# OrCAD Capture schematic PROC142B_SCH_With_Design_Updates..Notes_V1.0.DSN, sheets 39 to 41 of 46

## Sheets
39 39. OLDI DISPLAY INTERFACE: size C; title: SOC OLDI INTERFACE, LCD CONNECTOR & SOC UART1 FET SWITCH & BUFFER
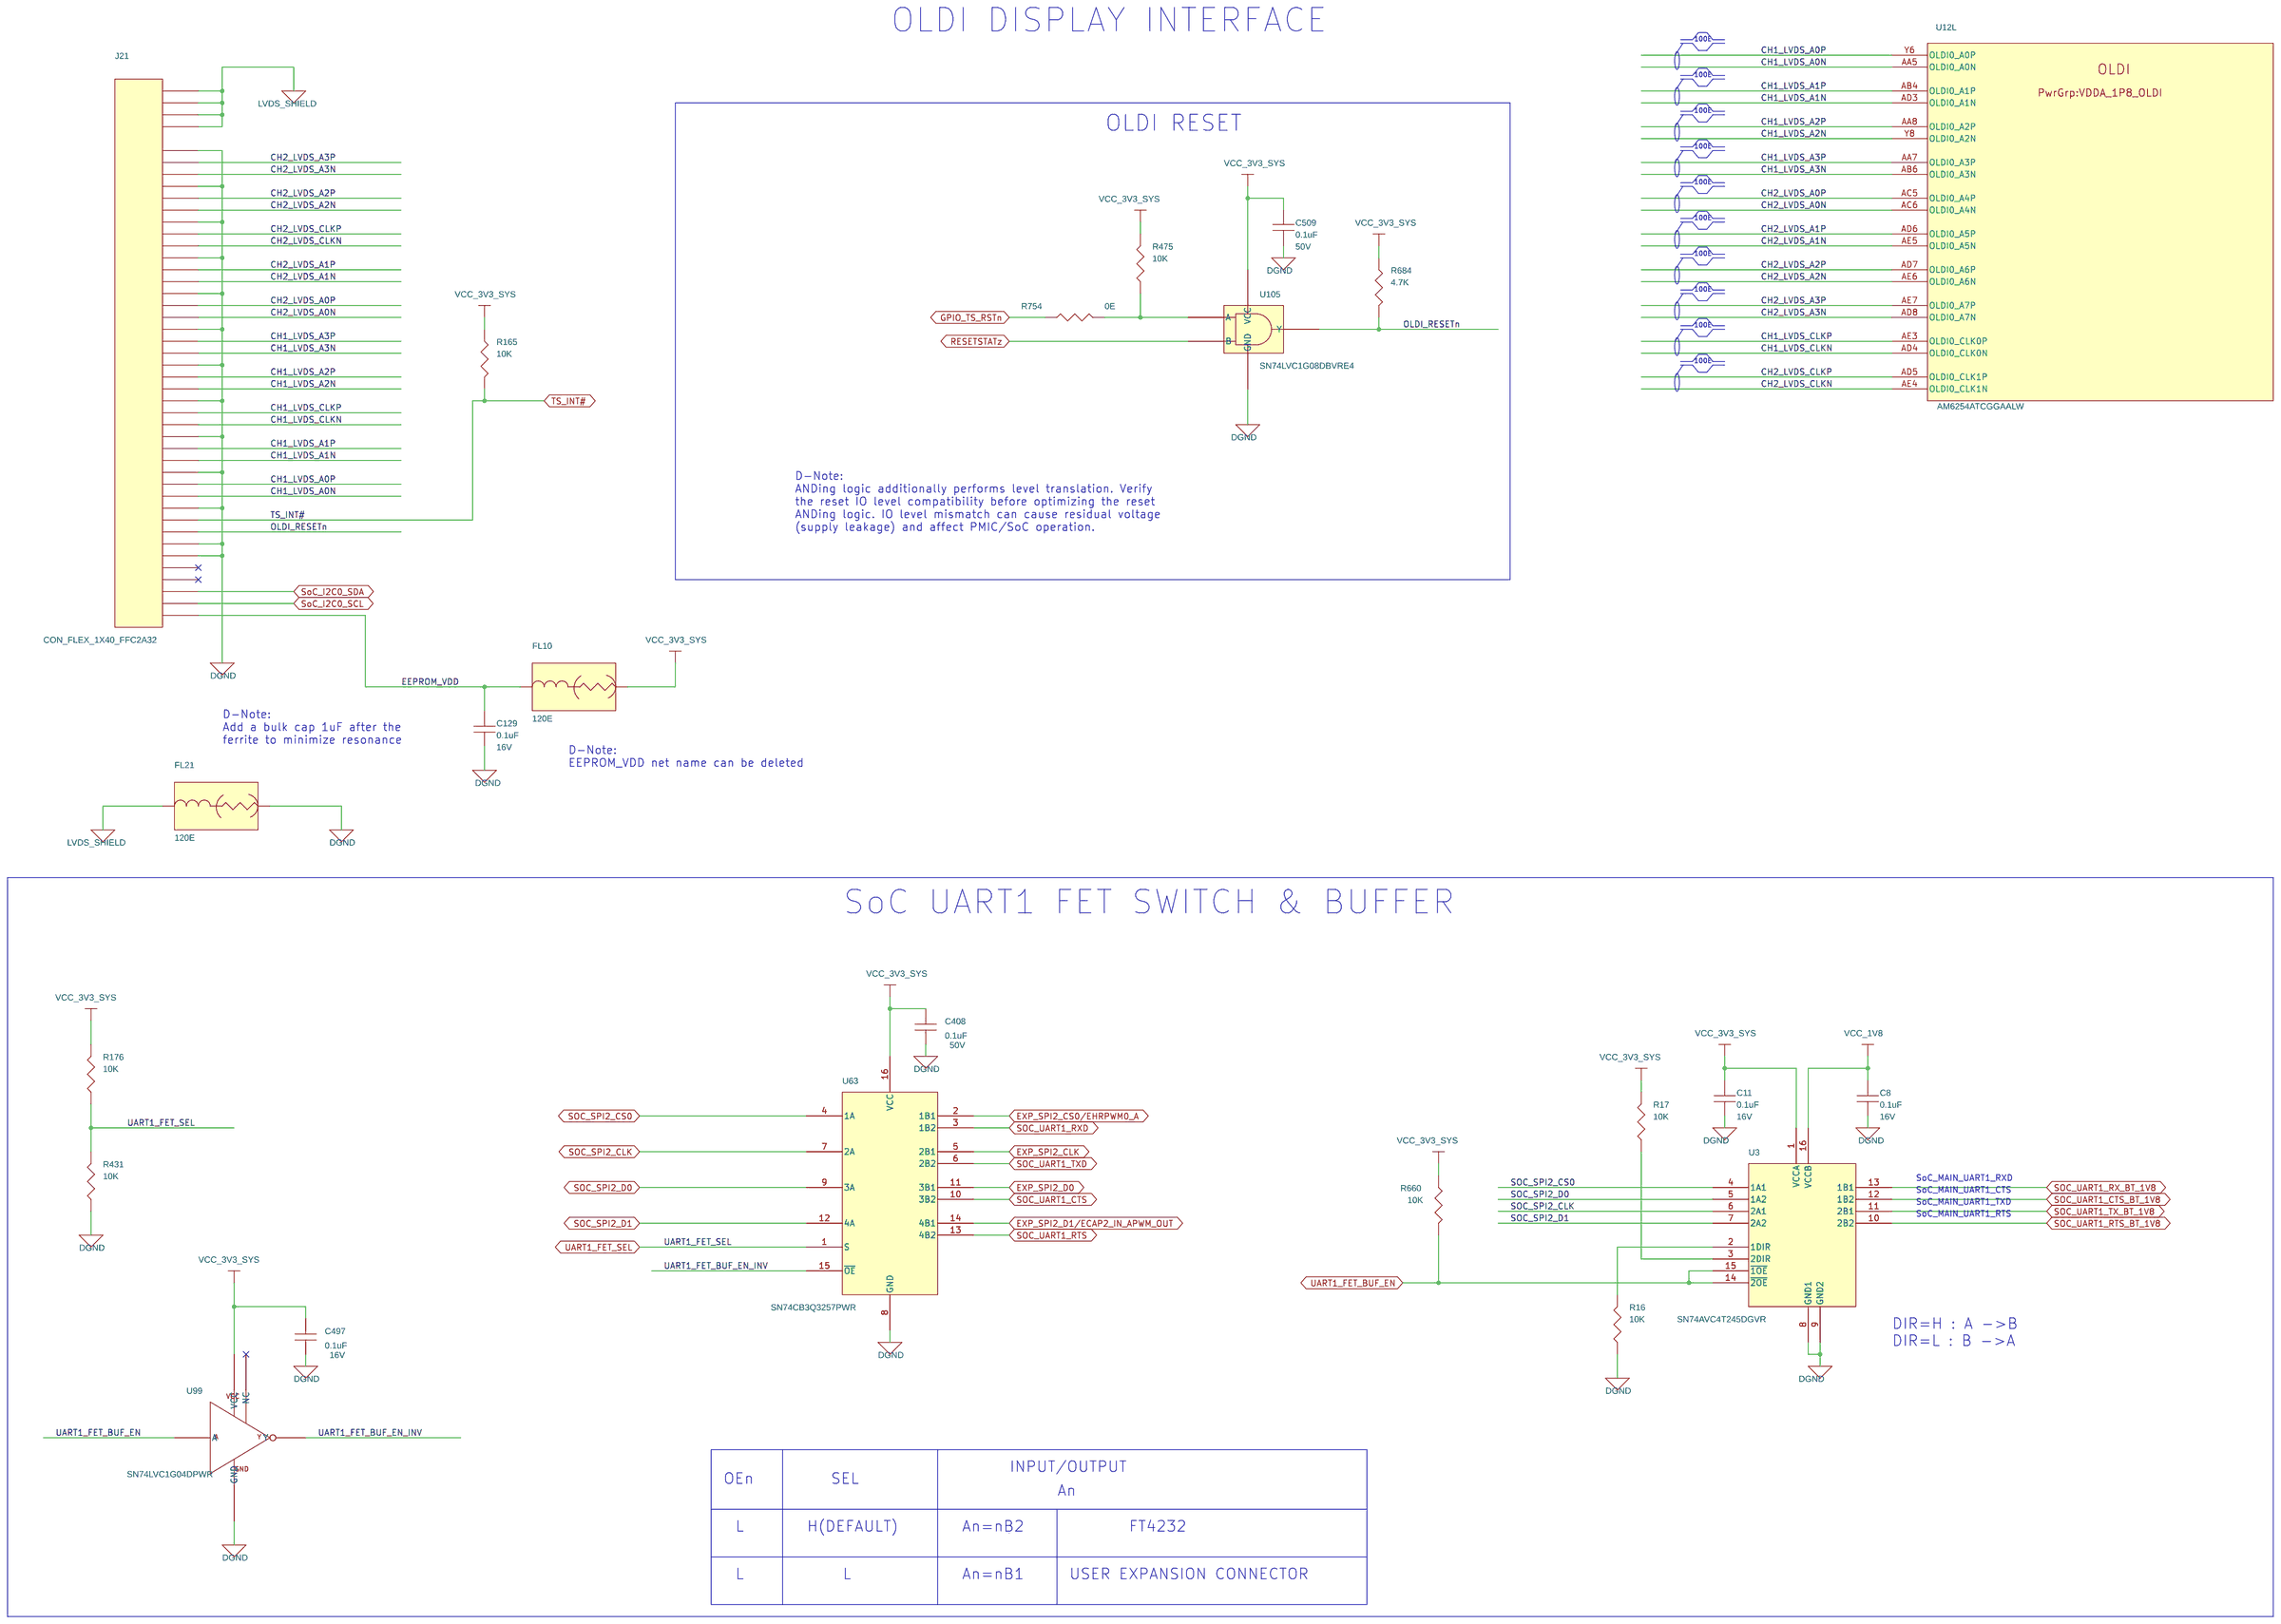
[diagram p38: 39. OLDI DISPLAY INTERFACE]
40 40. CSI INTERFACE & TEST LEDS: size C; title: SOC CSI INTERFACE AND CAMERA CONNECTOR
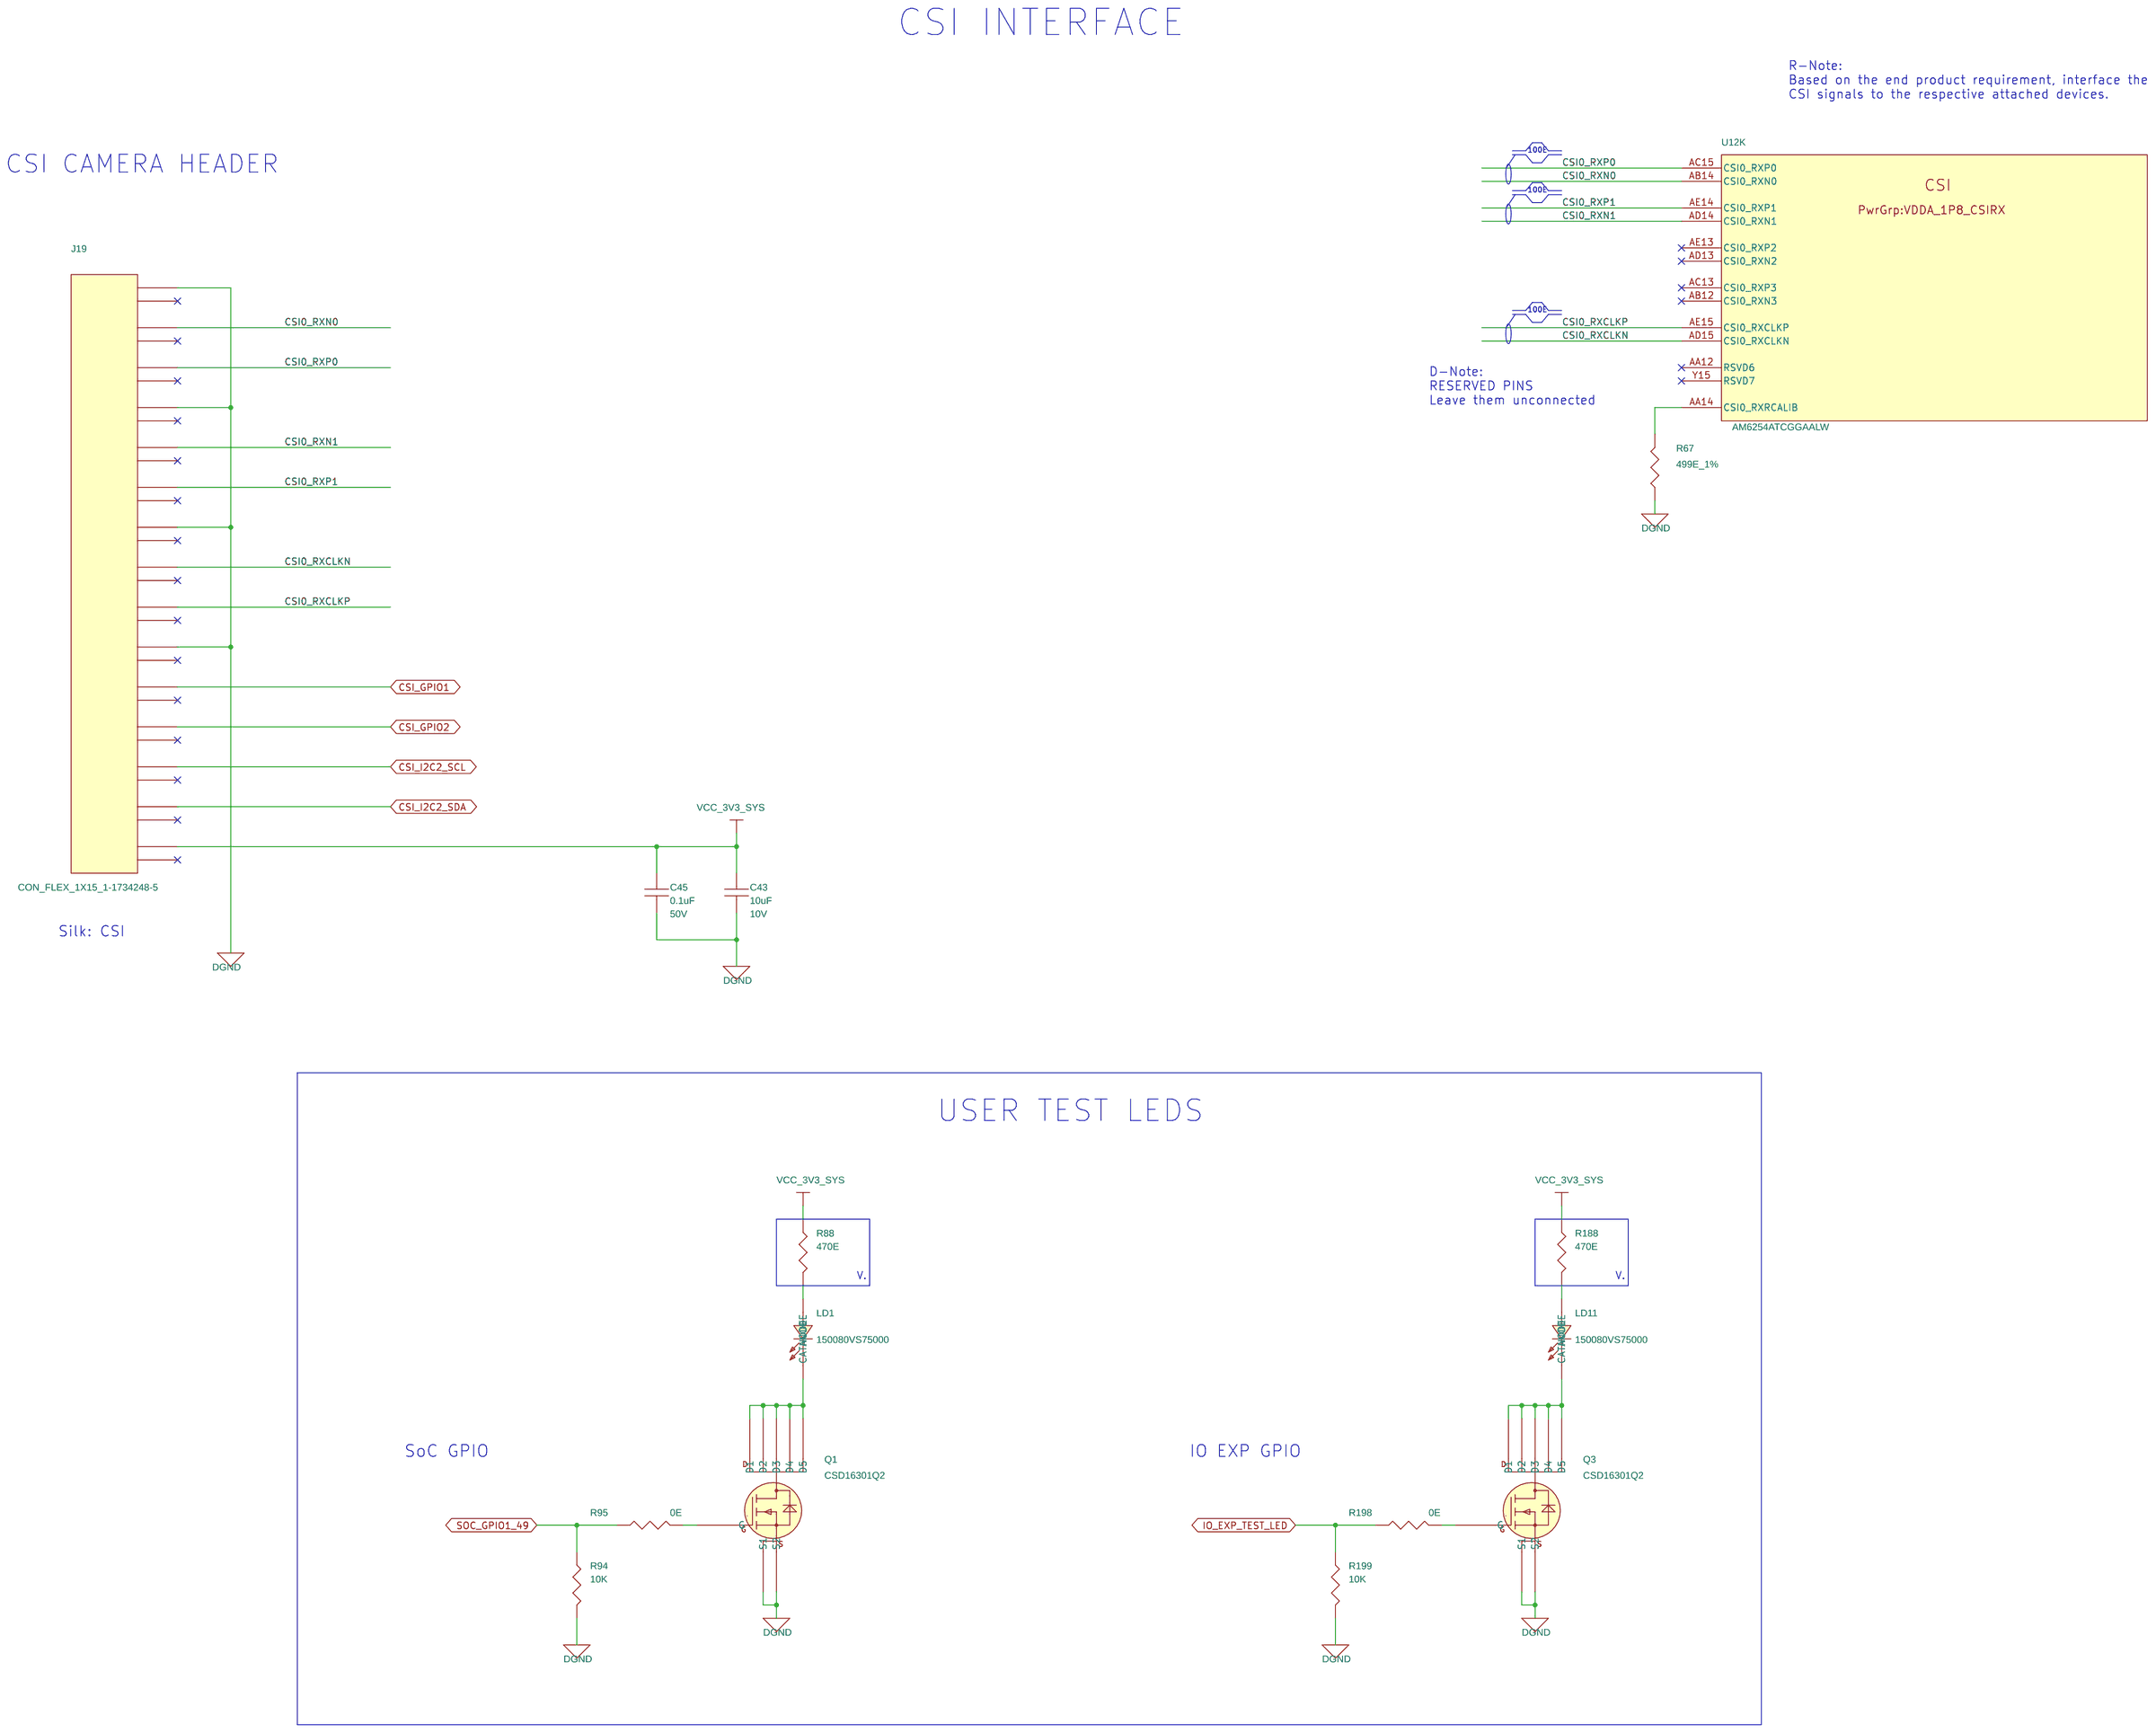
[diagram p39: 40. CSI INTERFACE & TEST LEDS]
41 41. IO EXPANDER: size C; title: IO EXPANDER AND MCASP1 FET SWITCH & BUFFER
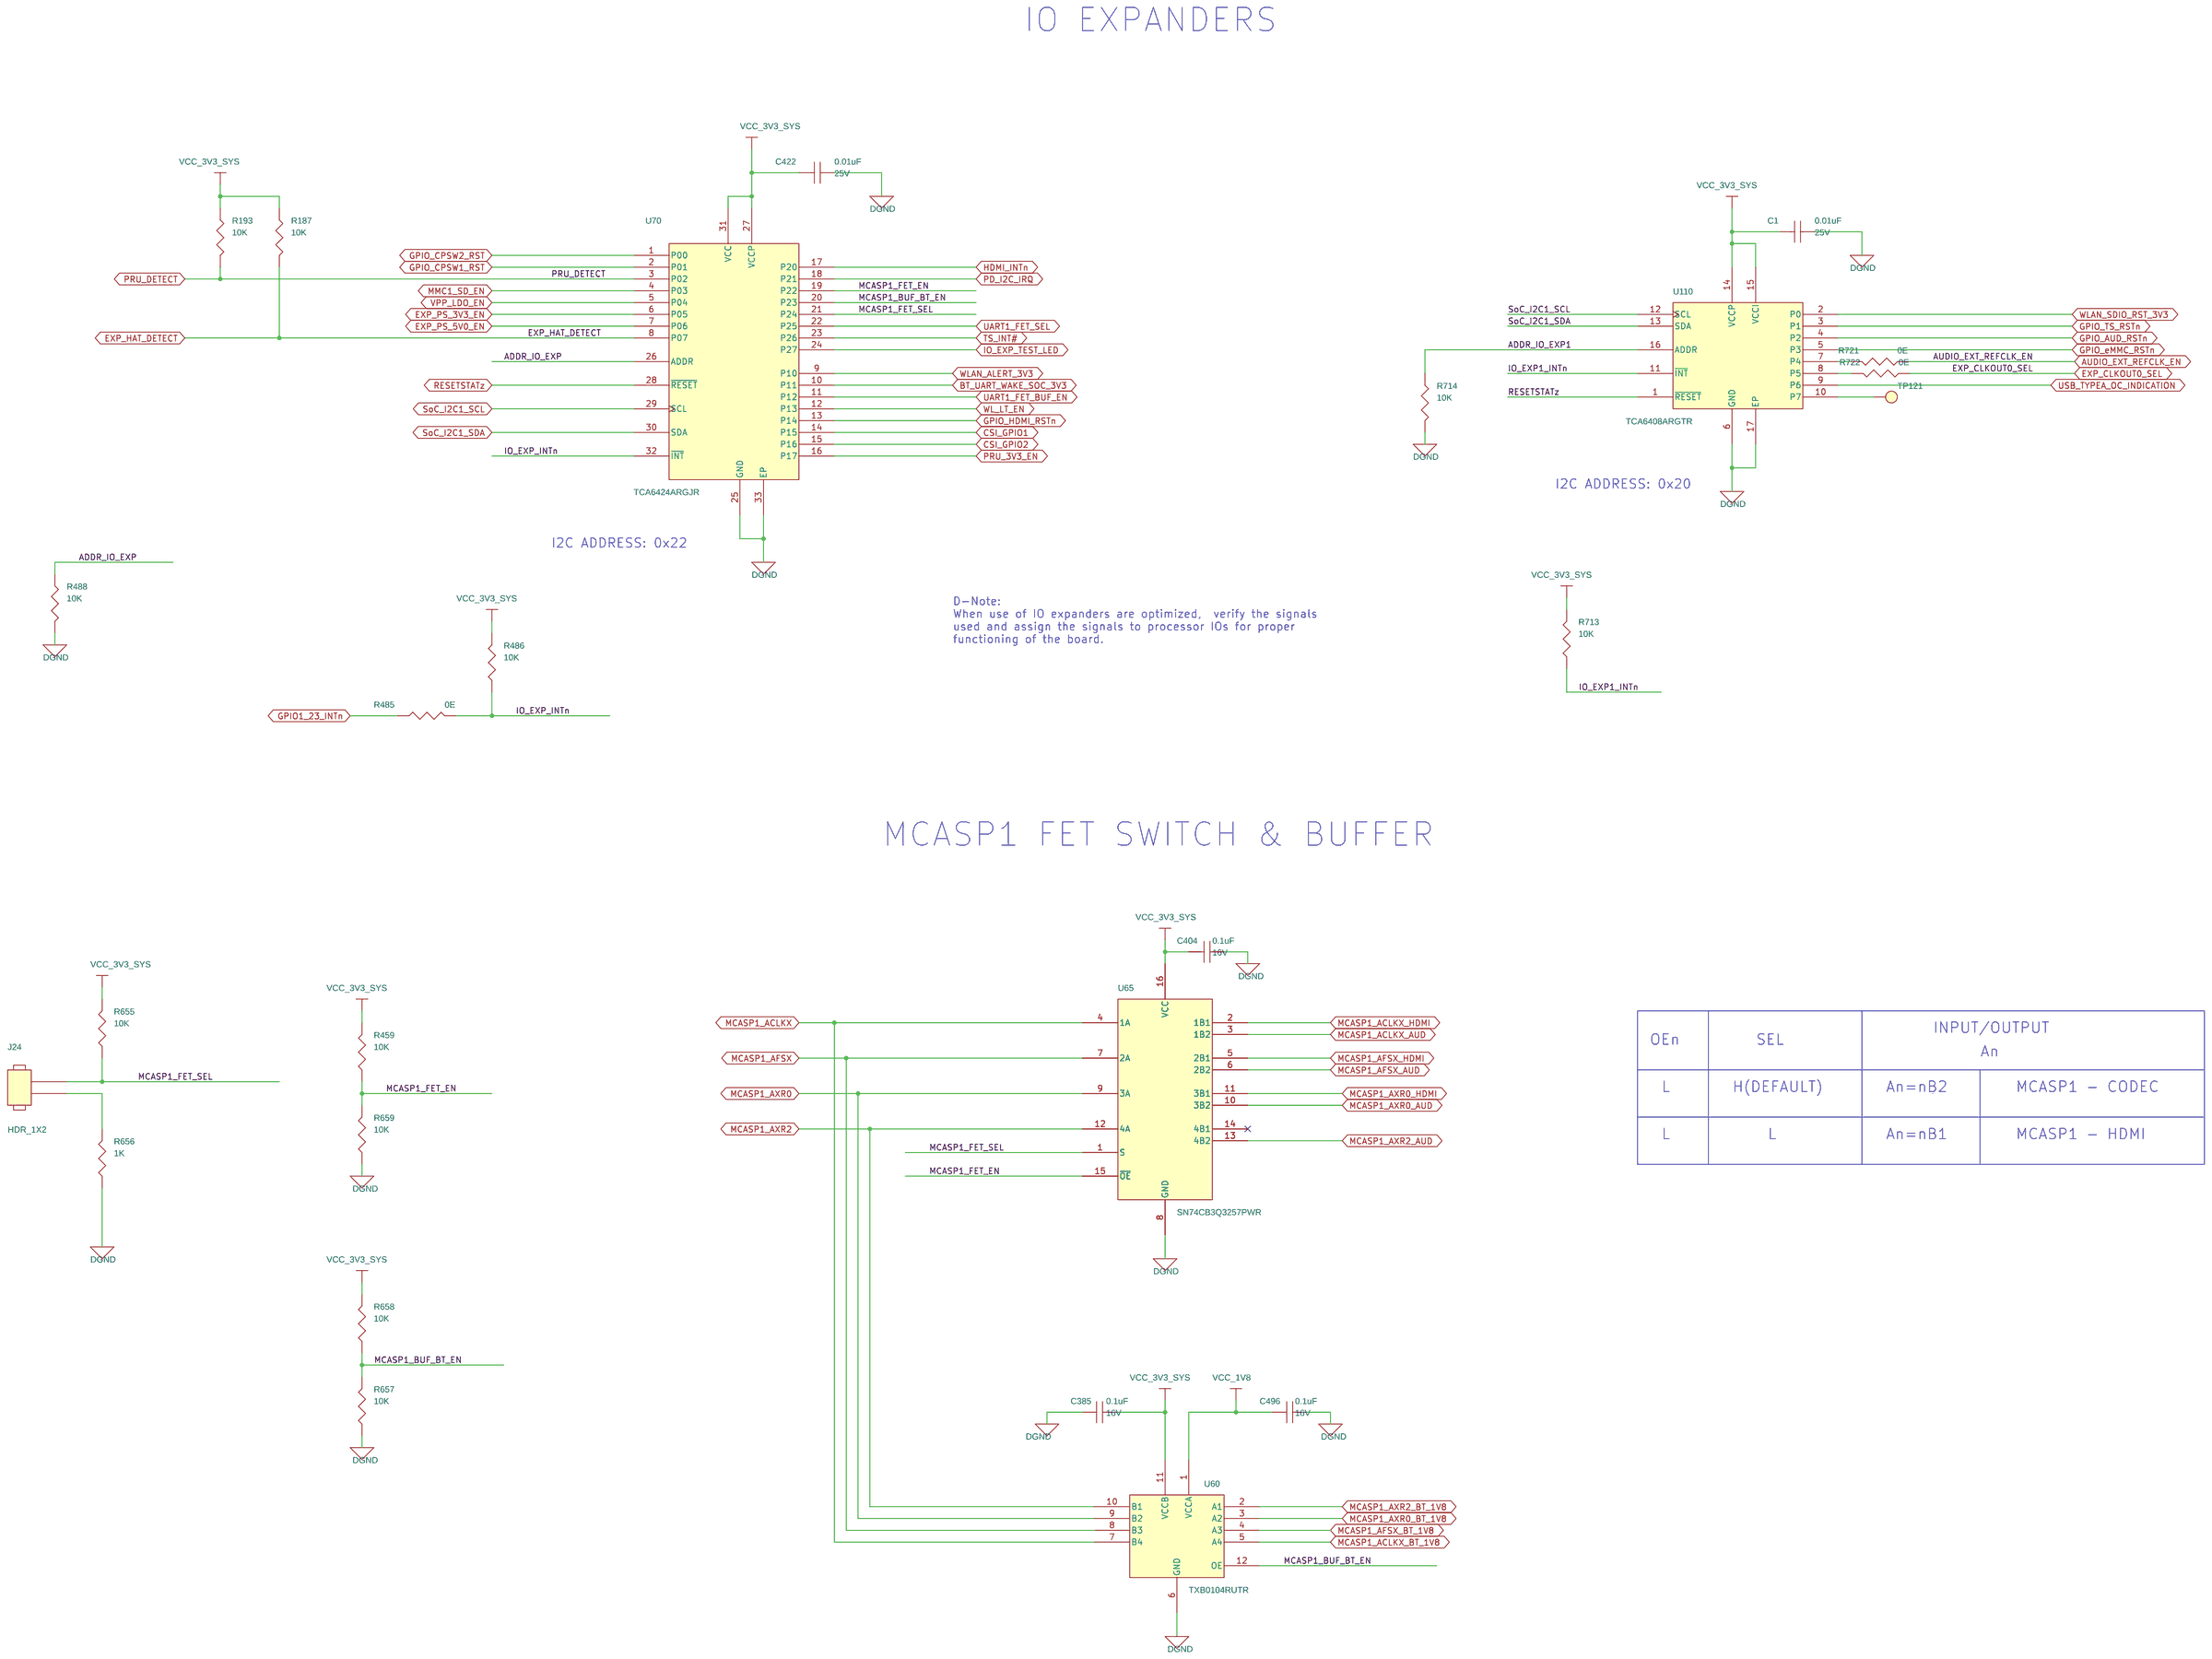
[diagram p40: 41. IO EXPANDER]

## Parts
sheet 39. OLDI DISPLAY INTERFACE
C8  0.1uF  [CAP0201_0-5]
C11  0.1uF  [CAP0201_0-5]
C129  0.1uF  [CAP0201_0-5]
C408  0.1uF  [CAP0402_0-75]
C497  0.1uF  [CAP0201_0-5]
C509  0.1uF  [CAP0402_0-75]
FL10  120E  [EMIFIL_BLM15A_0402_0-6]
FL21  120E  [EMIFIL_BLM15A_0402_0-6]
J21  CON_FLEX_1X40_FFC2A32  [CON_FLEX1X40_FFC2A32-40-T_S_S_S_4-3]
R16  10K  [RES0201_0-5]
R17  10K  [RES0201_0-5]
R165  10K  [RES0201_0-5]
R176  10K  [RES0201_0-5]
R431  10K  [RES0201_0-5]
R475  10K  [RES0201_0-5]
R660  10K  [RES0201_0-5]
R684  4.7K  [RES0201_0-5]
R754  0E  [RES0402_0-5]
U3  SN74AVC4T245DGVR  [TVSOP16_15-74_150X180]
U63  SN74CB3Q3257PWR  [TSSOP16_25-59_205X180]
U99  SN74LVC1G04DPWR  [X2SON5_TLV7021_30X30_0-4]
U105  SN74LVC1G08DBVRE4  [SOT23-5]
sheet 40. CSI INTERFACE & TEST LEDS
C43  10uF  [CAP0402_0-75]
C45  0.1uF  [CAP0402_0-75]
J19  CON_FLEX_1X15_1-1734248-5  [CON_FLEX1X15_1-1734248-5_S_S_S_7-7]
LD1  150080VS75000  [LED_150080VS75000_80X50_SMD_0-8]
LD11  150080VS75000  [LED_150080VS75000_80X50_SMD_0-8]
Q1  CSD16301Q2  [WSON6_CSD13202Q2_80X80_0-8]
Q3  CSD16301Q2  [WSON6_CSD13202Q2_80X80_0-8]
R67  499E_1%  [RES0402_0-5]
R88  470E  [RES0402_0-5]
R94  10K  [RES0201_0-5]
R95  0E  [RES0402_0-5]
R188  470E  [RES0402_0-5]
R198  0E  [RES0402_0-5]
R199  10K  [RES0201_0-5]
sheet 41. IO EXPANDER
C1  0.01uF  [CAP0201_0-5]
C385  0.1uF  [CAP0201_0-5]
C404  0.1uF  [CAP0201_0-5]
C422  0.01uF  [CAP0201_0-5]
C496  0.1uF  [CAP0201_0-5]
J24  HDR_1X2  [HDR_1X2_90120-0122_S_T_5-6]
R187  10K  [RES0201_0-5]
R193  10K  [RES0201_0-5]
R459  10K  [RES0201_0-5]
R485  0E  [RES0402_0-5]
R486  10K  [RES0201_0-5]
R488  10K  [RES0201_0-5]
R655  10K  [RES0201_0-5]
R656  1K  [RES0402_0-5]
R657  10K  [RES0201_0-5]
R658  10K  [RES0201_0-5]
R659  10K  [RES0201_0-5]
R713  10K  [RES0201_0-5]
R714  10K  [RES0201_0-5]
R721  0E  [RES0201_0-5]
R722  0E  [RES0201_0-5]
TP121  TP20_SMD  [TP20_SMD]
U60  TXB0104RUTR  [UQFN12_TXB0104RUT_70X80_0-6]
U65  SN74CB3Q3257PWR  [TSSOP16_25-59_205X180]
U70  TCA6424ARGJR  [QFN32_19-68_200X200]
U110  TCA6408ARGTR  [QFN16_19-68_120X120_1_EP1-6]
sheet 43. HDMI INTERFACE
U12  AM6254ATCGGAALW  [BGA425_19-68_510X510_0-7]  (sections A,B,C,D,E,F,G,H,I,J,K,L,M,N,O,P,Q,R)

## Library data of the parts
C8 C11 C129 C385 C404 C496 C497 = CAP: CAP CERAMIC 0.1uF 16V 10% X5R 0201; Alt_Mfr_name: YAGEO AMERICA; Alt_Mfr_part_number: CC0402KRX5R8BB104; Chkd/date: MANIRAJA/230118; Crtd /date: MANIRAJA/230118; Custom_Duty: 15%; Customs_HS_Code: 85322990; Distributor_name: DIGIKEY; Distributor_part_number: 490-14305-1-ND; Footprint Path: Y:\MIS_DATABASE\Library\ALTIUM_TOOL\PCB_FOOTPRINTS\Altium_Footprint_Lib.PcbLib; Height: 0.33MM; Library Path: Y:\MIS_DATABASE\Library\ALTIUM_TOOL\SCHEMATICS_PARTS\MS_DISCRETE_Library.schlib; Mfr_name: MURATA; Mfr_part_number: GRM033R61C104KE14D; Mistral Part No: 120009030072-R; Package: 0201; Part_type: CAPACITORS\CERAMIC; Project: TI_MAXIE_CPB; RoHS: RoHS; Temperature: -55°C+85°C; Tolerance: 10%; Voltage: 16V; Wattage: NA; Weight: 0.33mg; Datasheet: Y:\MIS_DATABASE\DATASHEETS\CAPACITORS\GRM033R61C104KE14.PDF
C45 C408 C509 = CAP: CAP CERAMIC 0.1uF 50V 10% X7R 0402; Alt_Mfr_name: YAGEO AMERICA; Alt_Mfr_part_number: CC0402KRX5R8BB104; Chkd/date: MANIRAJA/261020; Crtd /date: ALVY/211020; Custom_Duty: 15%; Customs_HS_Code: 85322990; Distributor_name: DIGIKEY; Distributor_part_number: 490-10700-1-ND; Footprint Path: Y:\MIS_DATABASE\Library\ALTIUM_TOOL\PCB_FOOTPRINTS\Altium_Footprint_Lib.PcbLib; Height: 0.55MM; Library Path: Y:\MIS_DATABASE\Library\ALTIUM_TOOL\SCHEMATICS_PARTS\MS_DISCRETE_Library.schlib; Mfr_name: MURATA; Mfr_part_number: GRM155R71H104KE14D; Mistral Part No: 120011100014-R; Package: 0402; Part_type: CAPACITORS\CERAMIC; Project: J7_CP; RoHS: RoHS; Temperature: -55°C+125°C; Tolerance: 10%; Voltage: 50V; Wattage: NA; Weight: 3.1mg; Datasheet: Y:\MIS_DATABASE\DATASHEETS\CAPACITORS\GRM155R71H104KE14.PDF
FL10 FL21 = EMIFILTER_IND: IND FERRITE BEAD CHIP 120E 2A 0402; Chkd/date: NAVEED/241114; Crtd /date: USMAN/170613; Custom_Duty: 24%; Customs_HS_Code: 85369090; Distributor_name: DIGIKEY; Distributor_part_number: 490-9656-1-ND; Footprint Path: Y:\MIS_DATABASE\Library\ALTIUM_TOOL\PCB_FOOTPRINTS\Altium_Footprint_Lib.PcbLib; Height: 0.55MM; Library Path: Y:\MIS_DATABASE\Library\ALTIUM_TOOL\SCHEMATICS_PARTS\MS_FILTER_Library.schlib; Mfr_name: MURATA; Mfr_part_number: BLM15PX121SN1D; Mistral Part No: 130013060022-R; Package: 0402; Part_type: INDUCTOR; Project: GEN_3-8; RoHS: RoHS; Temperature: -55°C+125°C; Tolerance: 25%; Voltage: NA; Wattage: NA; Weight: 1mg; Datasheet: Y:\MIS_DATABASE\DATASHEETS\DISCRETES\INDUCTORS\BLM15-SN1-SER.PDF
J21 = CON_FLEX_40X1_SH4: CON FPC 1X40 0.50MM PITCH FEMALE ST SMD; Chkd/date: MANIRAJA/061021; Crtd /date: ALVY/041021; Custom_Duty: 24%; Customs_HS_Code: 85369090; Distributor_name: DIGIKEY; Distributor_part_number: 2073-FFC2A32-40-TCT-ND; Footprint Path: Y:\MIS_DATABASE\Library\ALTIUM_TOOL\PCB_FOOTPRINTS\Altium_Footprint_Lib.PcbLib; Height: 4.25MM; Library Path: Y:\MIS_DATABASE\Library\ALTIUM_TOOL\SCHEMATICS_PARTS\MS_CONNECTOR_Library.schlib; Mfr_name: GCT; Mfr_part_number: FFC2A32-40-T; Mistral Part No: 150021100004-R; Package: SMD; Part_type: CONNECTOR\FPC; Project: TI_AM62x SKEVM_BRD; RoHS: RoHS; Temperature: -25°C+85°C; Tolerance: NA; Voltage: NA; Wattage: NA; Weight: 710mg; Datasheet: Y:\MIS_DATABASE\DATASHEETS\CONNECTORS\FFC2A32.PDF
R16 R17 R94 R165 R176 R187 R193 R199 R431 R459 R475 R486 R488 R655 R657-R660 R713 R714 = RESISTOR: RES 10K 1/20W 5% 0201; Chkd/date: MANIRAJA/050517; Crtd /date: MANIRAJA/050517; Custom_Duty: 15%; Customs_HS_Code: 85332119; Distributor_name: DIGIKEY; Distributor_part_number: 311-10KNCT-ND; Footprint Path: Y:\MIS_DATABASE\Library\ALTIUM_TOOL\PCB_FOOTPRINTS\Altium_Footprint_Lib.PcbLib; Height: 0.26MM; Library Path: Y:\MIS_DATABASE\Library\ALTIUM_TOOL\SCHEMATICS_PARTS\MS_DISCRETE_Library.schlib; Mfr_name: YAGEO AMERICA; Mfr_part_number: RC0201JR-0710KL; Mistral Part No: 110010070051-R; Package: 0201; Part_type: RESISTORS\FIXED; Project: GOLDEN-I LITE; RoHS: RoHS; Temperature: -55°C+125°C; Tolerance: 5%; Voltage: NA; Wattage: 1/20W; Weight: 0.17mg; Datasheet: Y:\MIS_DATABASE\DATASHEETS\RESISTORS\RCXXXXL-SER_MAR18.PDF
R684 = RESISTOR: RES 4.7K 1/20W 5% 0201; Chkd/date: MANIRAJA/200921; Crtd /date: ALVY/200921; Custom_Duty: 15%; Customs_HS_Code: 85332119; Distributor_name: DIGIKEY; Distributor_part_number: 311-4.7KNCT-ND; Footprint Path: Y:\MIS_DATABASE\Library\ALTIUM_TOOL\PCB_FOOTPRINTS\Altium_Footprint_Lib.PcbLib; Height: 0.26MM; Library Path: Y:\MIS_DATABASE\Library\ALTIUM_TOOL\SCHEMATICS_PARTS\MS_DISCRETE_Library.schlib; Mfr_name: YAGEO AMERICA; Mfr_part_number: RC0201JR-074K7L; Mistral Part No: 110021090007-R; Package: 0201; Part_type: RESISTORS\FIXED; Project: TI_AM62x SKEVM_BRD; RoHS: RoHS; Temperature: -55°C+125°C; Tolerance: 5%; Voltage: NA; Wattage: 1/20W; Weight: 0.17mg; Datasheet: Y:\MIS_DATABASE\DATASHEETS\RESISTORS\RCXXXXL-SER_MAR18.PDF
R95 R198 R485 R754 = RESISTOR: RES 0E 1/16W JUMPER 0402; Chkd/date: VASANTHA/201216; Crtd /date: MUDDU/190810; Custom_Duty: 15%; Customs_HS_Code: 85332119; Distributor_name: DIGIKEY; Distributor_part_number: 541-0.0JCT-ND; Footprint Path: Y:\MIS_DATABASE\Library\ALTIUM_TOOL\PCB_FOOTPRINTS\Altium_Footprint_Lib.PcbLib; Height: 0.40MM; Library Path: Y:\MIS_DATABASE\Library\ALTIUM_TOOL\SCHEMATICS_PARTS\MS_DISCRETE_Library.schlib; Mfr_name: VISHAY; Mfr_part_number: CRCW04020000Z0ED; Mistral Part No: 110010080019-R; Package: 0402; Part_type: RESISTORS\FIXED; Project: PB_BUGBASE; RoHS: RoHS; Temperature: -55°C+155°C; Tolerance: NA; Voltage: NA; Wattage: 1/16W; Weight: 0.65mg; Datasheet: Y:\MIS_DATABASE\DATASHEETS\RESISTORS\CRCW0603.PDF
U3 = SN74AVC4T245DGVR_TVSOP16: IC 4-BIT DUAL SUPPLY BUS TRANSCEIVER TVSOP16; Chkd/date: SUHAS/251010; Crtd /date: MAZHAR/201109; Custom_Duty: 15%; Customs_HS_Code: 85423100; Distributor_name: DIGIKEY; Distributor_part_number: 296-18054-1-ND; Height: 1.20MM; Mfr_name: TEXAS INSTRUMENTS; Mistral Part No: 141009110005-P; Package: TVSOP16; Part_type: ICS\DIGITAL\COMBINATIONAL; Project: GOLDEN-I; RoHS: Sb/ Br FREE; Temperature: -40°C+85°C; Datasheet: Y:\MIS_DATABASE\DATASHEETS\ICS\DIGITAL\BUSTRANSCEIVER\SN74AVC4T245.PDF
U63 = SN74CB3Q3257PWR_TSSOP16: IC 4BIT 1-OF-2 FET MULTIPLEXER/DEMULTIPLEXER TSSOP16; Chkd/date: SUHAS/251010; Crtd /date: USMAN/060109; Custom_Duty: 15%; Customs_HS_Code: 85423100; Distributor_name: DIGIKEY; Distributor_part_number: 296-19138-1-ND; Height: 1.20MM; Mfr_name: TEXAS INSTRUMENTS; Mistral Part No: 141009030117-R; Package: TSSOP16; Part_type: ICS\DIGITAL\COMBINATIONAL; Project: OMAP_EVM; RoHS: Sb/ Br FREE; Temperature: -40°C+85°C; Datasheet: Y:\MIS_DATABASE\DATASHEETS\ICS\DIGITAL\COMBINATIONAL\SN74CB3Q3257.PDF
U99 = SN74LVC1G04DCKR_SC70-5: IC SINGLE INVERTER GATE X2SON5; Chkd/date: MANIRAJA/141020; Crtd /date: ALVY/131020; Custom_Duty: 15%; Customs_HS_Code: 85423100; Distributor_name: DIGIKEY; Distributor_part_number: 296-37758-1-ND; Footprint Path: Y:\MIS_DATABASE\Library\ALTIUM_TOOL\PCB_FOOTPRINTS\Altium_Footprint_Lib.PcbLib; Height: 0.40MM; Library Path: Y:\MIS_DATABASE\Library\ALTIUM_TOOL\SCHEMATICS_PARTS\MS_GATE_Library.schlib; Mfr_name: TEXAS INSTRUMENTS; Mistral Part No: 141020100010-R; Package: X2SON5; Part_type: ICS\DIGITAL\GATES; Project: AM64X_SKEVM; RoHS: RoHS; Temperature: -40°C+125°C; Tolerance: NA; Voltage: NA; Wattage: NA; Weight: 0.6mg; Datasheet: Y:\MIS_DATABASE\DATASHEETS\ICS\DIGITAL\GATES\SN74LVC1G04XX.PDF
U105 = SN74LVC1G08DBVRE4_SOT23-5: IC SINGLE 2-INPUT POSITIVE AND GATE SOT23-5; Chkd/date: SUHAS/221010; Crtd /date: USMAN/151008; Custom_Duty: 15%; Customs_HS_Code: 85423100; Distributor_name: DIGIKEY; Distributor_part_number: SN74LVC1G08DBVRE4-ND; Height: 1.45MM; Mfr_name: TEXAS INSTRUMENTS; Mistral Part No: 141009060026-R; Part_type: ICS\DIGITAL\GATES; Project: KHAN_MAIN; RoHS: Sb/ Br FREE; Temperature: -40°C+85°C; Datasheet: Y:\MIS_DATABASE\DATASHEETS\ICS\DIGITAL\GATES\SN74LVC1G08.PDF
C43 = CAP: CAP CERAMIC 10uF 10V 20% X5R 0402; Chkd/date: MANIRAJA/300520; Crtd /date: ALVY/260520; Custom_Duty: 15%; Customs_HS_Code: 85322990; Distributor_name: DIGIKEY; Distributor_part_number: 490-GRM155R61A106ME11DTR-ND; Footprint Path: Y:\MIS_DATABASE\Library\ALTIUM_TOOL\PCB_FOOTPRINTS\Altium_Footprint_Lib.PcbLib; Height: 0.55MM; Library Path: Y:\MIS_DATABASE\Library\ALTIUM_TOOL\SCHEMATICS_PARTS\MS_DISCRETE_Library.schlib; Mfr_name: MURATA; Mfr_part_number: GRM155R61A106ME11D; Mistral Part No: 120013110019-R; Package: 0402; Part_type: CAPACITORS\CERAMIC; Project: QCS610_NANOSOM; RoHS: RoHS; Temperature: -55°C+85°C; Tolerance: 20%; Voltage: 10V; Wattage: NA; Weight: 3.1mg; Datasheet: Y:\MIS_DATABASE\DATASHEETS\CAPACITORS\MURATA-GXX-SER_NOV17.PDF
J19 = CON_FLEX_15X1_1-1734248-5: CON FPC 1X15 1.00MM PITCH FEMALE ST SMD; Chkd/date: ALVY/030620; Crtd /date: ALVY/030620; Custom_Duty: 24%; Customs_HS_Code: 85369090; Distributor_name: DIGIKEY; Distributor_part_number: A101418CT-ND; Footprint Path: Y:\MIS_DATABASE\Library\ALTIUM_TOOL\PCB_FOOTPRINTS\Altium_Footprint_Lib.PcbLib; Height: 7.70MM; Library Path: Y:\MIS_DATABASE\Library\ALTIUM_TOOL\SCHEMATICS_PARTS\MS_CONNECTOR_Library.schlib; Mfr_name: TE CONNECTIVITY; Mfr_part_number: 1-1734248-5; Mistral Part No: 150020060004-R; Package: SMD; Part_type: CONNECTOR\FPC; Project: JETSON_CARRIER_BRD; RoHS: RoHS; Temperature: -20°C+85°C; Tolerance: NA; Voltage: NA; Wattage: NA; Weight: 612mg; Datasheet: Y:\MIS_DATABASE\DATASHEETS\CONNECTORS\1734248.PDF
LD1 LD11 = DIODE_LED: DIODE LED BRIGHT GREEN SMD; Chkd/date: MANIRAJA/180820; Crtd /date: ALVY/180820; Custom_Duty: 24%; Customs_HS_Code: 85439000; Distributor_name: DIGIKEY; Distributor_part_number: 732-4986-1-ND; Footprint Path: Y:\MIS_DATABASE\Library\ALTIUM_TOOL\PCB_FOOTPRINTS\Altium_Footprint_Lib.PcbLib; Height: 0.80MM; Library Path: Y:\MIS_DATABASE\Library\ALTIUM_TOOL\SCHEMATICS_PARTS\MS_OPTO_Library.schlib; Mfr_name: WURTH ELECTRONICS; Mistral Part No: 130020080012-R; Package: SMD; Part_type: OPTO\LED; Project: AM64x_EVM_BRD; RoHS: RoHS; Temperature: -40°C+85°C; Tolerance: NA; Voltage: NA; Wattage: NA; Weight: 10mg; Datasheet: Y:\MIS_DATABASE\DATASHEETS\DISCRETES\LEDS\150080VS75000.PDF
Q1 Q3 = MOSFET_CSD17313Q2: IC MOSFET N-CHANNEL NEXFET 25V WSON6; Chkd/date: ALVY/071220; Crtd /date: MANIRAJA/071220; Custom_Duty: 15%; Customs_HS_Code: 85423100; Distributor_name: DIGIKEY; Distributor_part_number: 296-25260-1-ND; Footprint Path: Y:\MIS_DATABASE\Library\ALTIUM_TOOL\PCB_FOOTPRINTS\Altium_Footprint_Lib.PcbLib; Height: 0.80MM; Library Path: Y:\MIS_DATABASE\Library\ALTIUM_TOOL\SCHEMATICS_PARTS\MS_MOSFET_Library.schlib; Mfr_name: TEXAS INSTRUMENTS; Mistral Part No: 142020120008-R; Package: WSON6; Part_type: ICS\POWER\MOSFET; Project: TI_AM243x LP EVM; RoHS: RoHS; Temperature: -55°C+150°C; Tolerance: NA; Voltage: NA; Wattage: NA; Weight: 8.7mg; Datasheet: Y:\MIS_DATABASE\DATASHEETS\ICS\POWER\CSD16301Q2.PDF
R67 = RESISTOR: RES 499E 1/16W 1% 0402; Chkd/date: MANIRAJA/051020; Crtd /date: ALVY/051020; Custom_Duty: 15%; Customs_HS_Code: 85332119; Distributor_name: DIGIKEY; Distributor_part_number: 311-499LRCT-ND; Footprint Path: Y:\MIS_DATABASE\Library\ALTIUM_TOOL\PCB_FOOTPRINTS\Altium_Footprint_Lib.PcbLib; Height: 0.40MM; Library Path: Y:\MIS_DATABASE\Library\ALTIUM_TOOL\SCHEMATICS_PARTS\MS_DISCRETE_Library.schlib; Mfr_name: YAGEO AMERICA; Mfr_part_number: RC0402FR-07499RL; Mistral Part No: 110020080006-R; Package: 0402; Part_type: RESISTORS\FIXED; Project: AM64XX_EVM; RoHS: RoHS; Temperature: -55°C+155°C; Tolerance: 1%; Voltage: NA; Wattage: 1/16W; Weight: 0.65mg; Datasheet: Y:\MIS_DATABASE\DATASHEETS\RESISTORS\RCXXXXL-SER_MAR18.PDF
R88 R188 = RESISTOR: RES 470E 1/10W 5% 0402; Chkd/date: SHREESHAIL/24050; Crtd /date: MAZHAR/260706; Custom_Duty: 15%; Customs_HS_Code: 85332119; Distributor_name: DIGIKEY; Distributor_part_number: P470JCT-ND; Footprint Path: Y:\MIS_DATABASE\Library\ALTIUM_TOOL\PCB_FOOTPRINTS\Altium_Footprint_Lib.PcbLib; Height: 0.40MM; Library Path: Y:\MIS_DATABASE\Library\ALTIUM_TOOL\SCHEMATICS_PARTS\MS_DISCRETE_Library.schlib; Mfr_name: PANASONIC-ECG; Mfr_part_number: ERJ-2GEJ471X; Mistral Part No: 110009030859-R; Package: 0402; Part_type: RESISTORS\FIXED; Project: POWERBOX; RoHS: RoHS; Temperature: -55°C+155°C; Tolerance: 5%; Voltage: NA; Wattage: 1/10W; Weight: 0.8mg; Datasheet: Y:\MIS_DATABASE\DATASHEETS\RESISTORS\PAN-ERJSER_NOV17.PDF
C1 C422 = CAP: CAP CERAMIC 0.01uF 25V 10% X5R 0201; Chkd/date: MANIRAJA/230118; Crtd /date: MANIRAJA/230118; Custom_Duty: 15%; Customs_HS_Code: 85322990; Distributor_name: DIGIKEY; Distributor_part_number: GRM033R61E103KA12J-ND; Footprint Path: Y:\MIS_DATABASE\Library\ALTIUM_TOOL\PCB_FOOTPRINTS\Altium_Footprint_Lib.PcbLib; Height: 0.33MM; Library Path: Y:\MIS_DATABASE\Library\ALTIUM_TOOL\SCHEMATICS_PARTS\MS_DISCRETE_Library.schlib; Mfr_name: MURATA; Mfr_part_number: GRM033R61E103KA12J; Mistral Part No: 120018010007-R; Package: 0201; Part_type: CAPACITORS\CERAMIC; Project: TI_MAXIE_CPB; RoHS: RoHS; Temperature: -55°C+85°C; Tolerance: 10%; Voltage: 25V; Wattage: NA; Weight: 0.33mg; Datasheet: Y:\MIS_DATABASE\DATASHEETS\CAPACITORS\GRM033R61E103KA12.PDF
J24 = HEADER_2X1: CON HDR 1X2 2.54MM PITCH ST TH; Chkd/date: NAVEED/210714; Crtd /date: USMAN/031012; Custom_Duty: 24%; Customs_HS_Code: 85369090; Distributor_name: DIGIKEY; Distributor_part_number: WM8072-ND; Footprint Path: Y:\MIS_DATABASE\Library\ALTIUM_TOOL\PCB_FOOTPRINTS\Altium_Footprint_Lib.PcbLib; Height: 5.60MM; Library Path: Y:\MIS_DATABASE\Library\ALTIUM_TOOL\SCHEMATICS_PARTS\MS_CONNECTOR_Library.schlib; Mfr_name: MOLEX; Mfr_part_number: 90120-0122; Mistral Part No: 150012100005-R; Package: THRU-HOLE; Part_type: CONNECTOR\HEADERS; Project: NPOL_FEP; RoHS: RoHS; Temperature: -55°C+125°C; Tolerance: NA; Voltage: NA; Wattage: NA; Weight: 122mg; Datasheet: Y:\MIS_DATABASE\DATASHEETS\CONNECTORS\90120-XX.PDF
R656 = RESISTOR: RES 1K 1/10W 5% 0402; Chkd/date: VASANTHA/201216; Crtd /date: MAZHAR/230805; Custom_Duty: 15%; Customs_HS_Code: 85332119; Distributor_name: DIGIKEY; Distributor_part_number: P1.0KJCT-ND; Footprint Path: Y:\MIS_DATABASE\Library\ALTIUM_TOOL\PCB_FOOTPRINTS\Altium_Footprint_Lib.PcbLib; Height: 0.40MM; Library Path: Y:\MIS_DATABASE\Library\ALTIUM_TOOL\SCHEMATICS_PARTS\MS_DISCRETE_Library.schlib; Mfr_name: PANASONIC-ECG; Mfr_part_number: ERJ-2GEJ102X; Mistral Part No: 110009030400-R; Package: 0402; Part_type: RESISTORS\FIXED; Project: HSE; RoHS: RoHS; Temperature: -55°C+155°C; Tolerance: 5%; Voltage: NA; Wattage: 1/10W; Weight: 0.8mg; Datasheet: Y:\MIS_DATABASE\DATASHEETS\RESISTORS\PAN-ERJSER_NOV17.PDF
R721 R722 = RESISTOR: RES 0E 1/20W 5% 0201; Chkd/date: NAVEED/301214; Crtd /date: MUDDU/120710; Custom_Duty: 15%; Customs_HS_Code: 85332119; Distributor_name: DIGIKEY; Distributor_part_number: 311-0.0NCT-ND; Footprint Path: Y:\MIS_DATABASE\Library\ALTIUM_TOOL\PCB_FOOTPRINTS\Altium_Footprint_Lib.PcbLib; Height: 0.26MM; Library Path: Y:\MIS_DATABASE\Library\ALTIUM_TOOL\SCHEMATICS_PARTS\MS_DISCRETE_Library.schlib; Mfr_name: YAGEO AMERICA; Mfr_part_number: RC0201JR-070RL; Mistral Part No: 110010070067-R; Package: 0201; Part_type: RESISTORS\FIXED; Project: PB_BUGBASE; RoHS: RoHS; Temperature: -55°C+125°C; Tolerance: 5%; Voltage: NA; Wattage: 1/20W; Weight: 0.17mg; Datasheet: Y:\MIS_DATABASE\DATASHEETS\RESISTORS\RCXXXXL-SER_MAR18.PDF
TP121 = TESTPOINT: TESTPOINT CIR 20 SMD; Chkd/date: SHREESHAIL/171006; Crtd /date: MAZHAR/171006; Custom_Duty: NA; Customs_HS_Code: NA; Distributor_name: NA; Distributor_part_number: NA; Footprint Path: Y:\MIS_DATABASE\Library\ALTIUM_TOOL\PCB_FOOTPRINTS\Altium_Footprint_Lib.PcbLib; Height: NA; Library Path: Y:\MIS_DATABASE\Library\ALTIUM_TOOL\SCHEMATICS_PARTS\MS_DISCRETE_Library.schlib; MECHANICAL 3D STEP FILE: NA; Mfr_name: LOCAL; Mistral Part No: NA; Package: SMD; Project: BT MODULE_CSRBC04; RoHS: NA; Temperature: NA; Tolerance: NA; Voltage: NA; Wattage: NA; Weight: NA; Datasheet: NA
U60 = TXB0104RUTR_UQFN12: IC 4-BIT BIDIRECTIONAL VOLTAGE-LEVEL TRANSLATOR UQFN12; Chkd/date: MANIRAJA/281117; Crtd /date: ALVY/271117; Custom_Duty: 15%; Customs_HS_Code: 85423100; Distributor_name: DIGIKEY; Distributor_part_number: 296-25888-1-ND; Height: 0.55MM; Manufacturer: TEXAS INSTRUMENTS; Mistral Part No: 141017110007-R; Package: UQFN12; Part_type: ICS\INTERFACE\LEVEL TRANSLATOR; Project: RSAPR_TYPE-II_3U-SBC; RoHS: RoHS; Temperature: -40°C+85°C; Tolerance: NA; Voltage: NA; Wattage: NA; Weight: 4.70mg; Datasheet: Y:\MIS_DATABASE\DATASHEETS\ICS\INTERFACE\TXB0104.PDF
U65 = SN74CB3Q3257PWR_TSSOP16: IC 4BIT 1-OF-2 FET MULTIPLEXER/DEMULTIPLEXER TSSOP16; Chkd/date: SUHAS/251010; Crtd /date: USMAN/060109; Custom_Duty: 15%; Customs_HS_Code: 85423100; Distributor_name: DIGIKEY; Distributor_part_number: 296-19138-1-ND; Height: 1.20MM; Manufacturer: TEXAS INSTRUMENTS; Mistral Part No: 141009030117-R; Package: TSSOP16; Part_type: ICS\DIGITAL\COMBINATIONAL; Project: OMAP_EVM; RoHS: Sb/ Br FREE; Temperature: -40°C+85°C; Datasheet: Y:\MIS_DATABASE\DATASHEETS\ICS\DIGITAL\COMBINATIONAL\SN74CB3Q3257.PDF
U70 = TCA6424ARGJR_QFN32: IC I2C I/O EXPANDER 24B UQFN32; Chkd/date: NAVEED/100715; Crtd /date: NAVEED/100914; Custom_Duty: 15%; Customs_HS_Code: 85423100; Distributor_name: DIGIKEY; Distributor_part_number: 296-27844-1-ND; Height: 0.60MM; Mfr_name: TEXAS INSTRUMENTS; Mistral Part No: 141014090009-R; Package: UQFN32; Part_type: ICS\DIGITAL\BUSTRANSCEIVER; Project: ZK_BIOMETRIC; RoHS: RoHS; Temperature: -40°C+85°C; Weight: NA; Datasheet: Y:\MIS_DATABASE\DATASHEETS\ICS\DIGITAL\BUSTRANSCEIVER\TCA6424AR.PDF
U110 = TCA6408ARGTR_VQFN16: IC 8-BIT I2C AND SMBUS I/O EXPANDER WITH INTERRUPT O/P VQFN16; Chkd/date: MANIRAJA/151018; Crtd /date: MANIRAJA/151018; Custom_Duty: 15%; Customs_HS_Code: 85423100; Distributor_name: DIGIKEY; Distributor_part_number: 296-24825-1-ND; Footprint Path: Y:\MIS_DATABASE\Library\ALTIUM_TOOL\PCB_FOOTPRINTS\Altium_Footprint_Lib.PcbLib; Height: 1.00MM; Library Path: Y:\MIS_DATABASE\Library\ALTIUM_TOOL\SCHEMATICS_PARTS\MS_MISCINTERFACE_Library.schlib; Mfr_name: TEXAS INSTRUMENTS; Mistral Part No: 141018100011-R; Package: VQFN16; Part_type: ICS\INTERFACE; Project: TI_60GHz-AOP; RoHS: RoHS; Temperature: -40°C+85°C; Tolerance: NA; Voltage: NA; Wattage: NA; Weight: 24.1mg; Datasheet: Y:\MIS_DATABASE\DATASHEETS\ICS\INTERFACE\TCA6408AXX.PDF
U12 = AM62-EVM_BGA425: IC AM62 SoC MICROPROCESSOR BGA425; Chkd/date: ALVY/110621; Crtd /date: MANIRAJA/110621; Custom_Duty: 15%; Customs_HS_Code: 85423100; Distributor_name: NA; Distributor_part_number: NA; Footprint Path: Y:\MIS_DATABASE\Library\ALTIUM_TOOL\PCB_FOOTPRINTS\Altium_Footprint_Lib.PcbLib; Height: 0.65MM; Library Path: Y:\MIS_DATABASE\Library\ALTIUM_TOOL\SCHEMATICS_PARTS\MS_MICROPROCESSOR_Library.schlib; Mfr_name: TEXAS INSTRUMENTS; Mistral Part No: 141221060001; Package: BGA425; Part_type: ICS\DIGITAL\MICROPROCESSOR; Project: AM62_EVM_BRD; RoHS: NA; Temperature: NA; Tolerance: NA; Voltage: NA; Wattage: NA; Weight: NA; Datasheet: Y:\MIS_DATABASE\DATASHEETS\ICS\DIGITAL\MICROCONTROLLER\AM62-SoC_SVB.PDF

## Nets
DGND: C1.1 C8.1 C11.1 C43.2 C45.2 C129.1 C385.1 C404.1 C408.1 C422.1 C496.1 C497.1 C509.2 FL21.2 J19.1A J19.4A J19.7A J19.10A J21.6 J21.7 J21.10 J21.13 J21.16 J21.19 J21.22 J21.25 J21.28 J21.31 J21.34 J21.37 J21.40 Q1.4(S1) Q1.7(S2) Q3.4(S1) Q3.7(S2) R16.1 R67.1 R94.1 R199.1 R431.1 R488.1 R656.1 R657.1 R659.1 R714.1 U3.8(GND1) U3.9(GND2) U60.6(GND) U63.8(GND) U65.8(GND) U70.25(GND) U70.33(EP) U99.3(GND) U105.3(GND) U110.6(GND) U110.17(EP) ; also on sheet 1 3 12 13 14 15 16 17 18 19 20 21 22 23 24 25 26 27 28 29 30 31 32 33 34 35 36 37 38 42 43 44 45
VCC_1V8: C8.2 C496.2 U3.16(VCCB) U60.1(VCCA) ; also on sheet 14 15 20 21 23 27 36 42 44
VCC_3V3_SYS: C1.2 C11.2 C43.1 C45.1 C385.2 C404.2 C408.2 C422.2 C497.2 C509.1 FL10.2 J19.15A R17.2 R88.1 R165.1 R176.2 R187.2 R188.1 R193.2 R459.2 R475.1 R486.2 R655.2 R658.2 R660.2 R684.1 R713.2 U3.1(VCCA) U60.11(VCCB) U63.16(VCC) U65.16(VCC) U70.27(VCCP) U70.31(VCC) U99.5(VCC) U105.5(VCC) U110.14(VCCP) U110.15(VCCI) ; also on sheet 3 12 14 15 16 20 21 22 24 25 26 27 28 29 31 32 33 34 35 36 37 38 42 43 44 45
ADDR_IO_EXP: R488.2 U70.26(ADDR)
ADDR_IO_EXP1: R714.2 U110.16(ADDR)
AUDIO_EXT_REFCLK_EN: R721.1 ; also on sheet 35
BT_UART_WAKE_SOC_3V3: U70.10(P11) ; also on sheet 20
CH1_LVDS_A0N: J21.11 U12.AA5(OLDI0_A0N)
CH1_LVDS_A0P: J21.12 U12.Y6(OLDI0_A0P)
CH1_LVDS_A1N: J21.14 U12.AD3(OLDI0_A1N)
CH1_LVDS_A1P: J21.15 U12.AB4(OLDI0_A1P)
CH1_LVDS_A2N: J21.20 U12.Y8(OLDI0_A2N)
CH1_LVDS_A2P: J21.21 U12.AA8(OLDI0_A2P)
CH1_LVDS_A3N: J21.23 U12.AB6(OLDI0_A3N)
CH1_LVDS_A3P: J21.24 U12.AA7(OLDI0_A3P)
CH1_LVDS_CLKN: J21.17 U12.AD4(OLDI0_CLK0N)
CH1_LVDS_CLKP: J21.18 U12.AE3(OLDI0_CLK0P)
CH2_LVDS_A0N: J21.26 U12.AC6(OLDI0_A4N)
CH2_LVDS_A0P: J21.27 U12.AC5(OLDI0_A4P)
CH2_LVDS_A1N: J21.29 U12.AE5(OLDI0_A5N)
CH2_LVDS_A1P: J21.30 U12.AD6(OLDI0_A5P)
CH2_LVDS_A2N: J21.35 U12.AE6(OLDI0_A6N)
CH2_LVDS_A2P: J21.36 U12.AD7(OLDI0_A6P)
CH2_LVDS_A3N: J21.38 U12.AD8(OLDI0_A7N)
CH2_LVDS_A3P: J21.39 U12.AE7(OLDI0_A7P)
CH2_LVDS_CLKN: J21.32 U12.AE4(OLDI0_CLK1N)
CH2_LVDS_CLKP: J21.33 U12.AD5(OLDI0_CLK1P)
CSI0_RXCLKN: J19.8A U12.AD15(CSI0_RXCLKN)
CSI0_RXCLKP: J19.9A U12.AE15(CSI0_RXCLKP)
CSI0_RXN0: J19.2A U12.AB14(CSI0_RXN0)
CSI0_RXN1: J19.5A U12.AD14(CSI0_RXN1)
CSI0_RXP0: J19.3A U12.AC15(CSI0_RXP0)
CSI0_RXP1: J19.6A U12.AE14(CSI0_RXP1)
CSI_GPIO1: J19.11A U70.14(P15)
CSI_GPIO2: J19.12A U70.15(P16)
CSI_I2C2_SCL: J19.13A ; also on sheet 35
CSI_I2C2_SDA: J19.14A ; also on sheet 35
EEPROM_VDD: C129.2 FL10.1 J21.1
EXP_CLKOUT0_SEL: R722.1 ; also on sheet 35
EXP_HAT_DETECT: R187.1 U70.8(P07) ; also on sheet 35
EXP_PS_3V3_EN: U70.6(P05) ; also on sheet 35
EXP_PS_5V0_EN: U70.7(P06) ; also on sheet 35
EXP_SPI2_CLK: U63.5(2B1) ; also on sheet 35
EXP_SPI2_CS0/EHRPWM0_A: U63.2(1B1) ; also on sheet 35
EXP_SPI2_D0: U63.11(3B1) ; also on sheet 35
EXP_SPI2_D1/ECAP2_IN_APWM_OUT: U63.14(4B1) ; also on sheet 35
GPIO1_23_INTn: R485.1 ; also on sheet 44 45
GPIO_AUD_RSTn: U110.4(P2) ; also on sheet 42
GPIO_CPSW1_RST: U70.2(P01) ; also on sheet 25
GPIO_CPSW2_RST: U70.1(P00) ; also on sheet 26
GPIO_eMMC_RSTn: U110.5(P3) ; also on sheet 21
GPIO_HDMI_RSTn: U70.13(P14) ; also on sheet 43
GPIO_TS_RSTn: R754.2 U110.3(P1)
HDMI_INTn: U70.17(P20) ; also on sheet 43
IO_EXP1_INTn: R713.1 U110.11(~{INT})
IO_EXP_INTn: R485.2 R486.1 U70.32(~{INT})
IO_EXP_TEST_LED: R198.1 R199.2 U70.24(P27)
LVDS_SHIELD: FL21.1 J21.SH1 J21.SH2 J21.SH3 J21.SH4
MCASP1_ACLKX: U60.7(B4) U65.4(1A) ; also on sheet 34
MCASP1_ACLKX_AUD: U65.3(1B2) ; also on sheet 42
MCASP1_ACLKX_BT_1V8: U60.5(A4) ; also on sheet 20
MCASP1_ACLKX_HDMI: U65.2(1B1) ; also on sheet 43
MCASP1_AFSX: U60.8(B3) U65.7(2A) ; also on sheet 34
MCASP1_AFSX_AUD: U65.6(2B2) ; also on sheet 42
MCASP1_AFSX_BT_1V8: U60.4(A3) ; also on sheet 20
MCASP1_AFSX_HDMI: U65.5(2B1) ; also on sheet 43
MCASP1_AXR0: U60.9(B2) U65.9(3A) ; also on sheet 34
MCASP1_AXR0_AUD: U65.10(3B2) ; also on sheet 42
MCASP1_AXR0_BT_1V8: U60.3(A2) ; also on sheet 20
MCASP1_AXR0_HDMI: U65.11(3B1) ; also on sheet 43
MCASP1_AXR2: U60.10(B1) U65.12(4A) ; also on sheet 34
MCASP1_AXR2_AUD: U65.13(4B2) ; also on sheet 42
MCASP1_AXR2_BT_1V8: U60.2(A1) ; also on sheet 20
MCASP1_BUF_BT_EN: R657.2 R658.1 U60.12(OE) U70.20(P23)
MCASP1_FET_EN: R459.1 R659.2 U65.15(~{OE}) U70.19(P22)
MCASP1_FET_SEL: J24.1 R655.1 U65.1(S) U70.21(P24)
MMC1_SD_EN: U70.4(P03) ; also on sheet 22
OLDI_RESETn: J21.8 R684.2 U105.4(Y)
PD_I2C_IRQ: U70.18(P21) ; also on sheet 12
PRU_3V3_EN: U70.16(P17) ; also on sheet 34
PRU_DETECT: R193.1 U70.3(P02) ; also on sheet 34
RESETSTATz: U70.28(~{RESET}) U105.2(B) U110.1(~{RESET}) ; also on sheet 15 21 22 23 25 26 29 34 35 42 43 44
SOC_GPIO1_49: R94.2 R95.1 ; also on sheet 21
SoC_I2C0_SCL: J21.2 ; also on sheet 12 15 24 34 35 44
SoC_I2C0_SDA: J21.3 ; also on sheet 12 15 24 34 35 44
SOC_I2C1_SCL: U70.29(SCL) U110.12(SCL) ; also on sheet 3 16 24 28 42 43 44
SOC_I2C1_SDA: U70.30(SDA) U110.13(SDA) ; also on sheet 3 16 24 28 42 43 44
SOC_SPI2_CLK: U3.6(2A1) U63.7(2A) ; also on sheet 35
SOC_SPI2_CS0: U3.4(1A1) U63.4(1A) ; also on sheet 35
SOC_SPI2_D0: U3.5(1A2) U63.9(3A) ; also on sheet 35
SOC_SPI2_D1: U3.7(2A2) U63.12(4A) ; also on sheet 35
SOC_UART1_CTS: U63.10(3B2) ; also on sheet 33
SOC_UART1_CTS_BT_1V8: U3.12(1B2) ; also on sheet 20
SOC_UART1_RTS: U63.13(4B2) ; also on sheet 33
SOC_UART1_RTS_BT_1V8: U3.10(2B2) ; also on sheet 20
SOC_UART1_RX_BT_1V8: U3.13(1B1) ; also on sheet 20
SOC_UART1_RXD: U63.3(1B2) ; also on sheet 33
SOC_UART1_TX_BT_1V8: U3.11(2B1) ; also on sheet 20
SOC_UART1_TXD: U63.6(2B2) ; also on sheet 33
TS_INT#: J21.9 R165.2 U70.23(P26)
UART1_FET_BUF_EN: R660.1 U3.14(~{2OE}) U3.15(~{1OE}) U70.11(P12) U99.2(A)
UART1_FET_BUF_EN_INV: U63.15(~{OE}) U99.4(Y)
UART1_FET_SEL: R176.1 R431.2 U63.1(S) U70.22(P25)
USB_TYPEA_OC_INDICATION: U110.9(P6) ; also on sheet 38
VPP_LDO_EN: U70.5(P04) ; also on sheet 14
WL_LT_EN: U70.12(P13) ; also on sheet 20
WLAN_ALERT_3V3: U70.9(P10) ; also on sheet 20
WLAN_SDIO_RST_3V3: U110.2(P0) ; also on sheet 20
N16925380: R67.2 U12.AA14(CSI0_RXRCALIB)
N18904630: LD1.1(CATHODE) Q1.1(D1) Q1.2(D2) Q1.5(D3) Q1.6(D4) Q1.8(D5)
N18904632: Q1.3(G) R95.2
N18904656: LD1.2(ANODE) R88.2
N18904815: LD11.1(CATHODE) Q3.1(D1) Q3.2(D2) Q3.5(D3) Q3.6(D4) Q3.8(D5)
N18904817: Q3.3(G) R198.2
N18904841: LD11.2(ANODE) R188.2
N19118228: R475.2 R754.1 U105.1(A)
N20066520: J24.2 R656.2
N20704463: R16.2 U3.2(1DIR)
N20704480: R17.1 U3.3(2DIR)
N20717880: TP121.1(TP) U110.10(P7)
N21985419: R721.2 U110.7(P4)
N21985445: R722.2 U110.8(P5)

Not connected (* = marked no-connect by the designer): J19 1B* 2B* 3B* 4B* 5B* 6B* 7B* 8B* 9B* 10B* 11B* 12B* 13B* 14B* 15B*; J21 4* 5*; U12 AA12(RSVD6)* AB12(CSI0_RXN3)* AC13(CSI0_RXP3)* AD13(CSI0_RXN2)* AE13(CSI0_RXP2)* Y15(RSVD7)*; U65 14(4B1)*; U99 1(NC)*

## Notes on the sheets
sheet 39
- OLDI DISPLAY INTERFACE
- 100E
- 100E
- 100E
- OLDI RESET
- 100E
- 100E
- 100E
- 100E
- 100E
- 100E
- 100E
- D-Note:
  ANDing logic additionally performs level translation. Verify
  the reset IO level compatibility before optimizing the reset
  ANDing logic. IO level mismatch can cause residual voltage
  (supply leakage) and affect PMIC/SoC operation.
- D-Note:
  Add a bulk cap 1uF after the
  ferrite to minimize resonance
- D-Note:
  EEPROM_VDD net name can be deleted
- SoC UART1 FET SWITCH & BUFFER
- SoC_MAIN_UART1_RXD
- SoC_MAIN_UART1_CTS
- SoC_MAIN_UART1_TXD
- SoC_MAIN_UART1_RTS
- DIR=H : A ->B
  DIR=L : B ->A
- INPUT/OUTPUT
- OEn
- SEL
- An
- L
- H(DEFAULT)
- An=nB2
- FT4232
- L
- L
- An=nB1
- USER EXPANSION CONNECTOR
sheet 40
- CSI INTERFACE
- R-Note:
  Based on the end product requirement, interface the
  CSI signals to the respective attached devices.
- CSI CAMERA HEADER
- 100E
- 100E
- 100E
- D-Note:
  RESERVED PINS
  Leave them unconnected
- Silk: CSI
- USER TEST LEDS
- V.
- V.
- SoC GPIO
- IO EXP GPIO
sheet 41
- IO EXPANDERS
- I2C ADDRESS: 0x20
- I2C ADDRESS: 0x22
- D-Note:
  When use of IO expanders are optimized,  verify the signals
  used and assign the signals to processor IOs for proper
  functioning of the board.
- MCASP1 FET SWITCH & BUFFER
- INPUT/OUTPUT
- OEn
- SEL
- An
- L
- H(DEFAULT)
- An=nB2
- MCASP1 - CODEC
- L
- L
- An=nB1
- MCASP1 - HDMI
